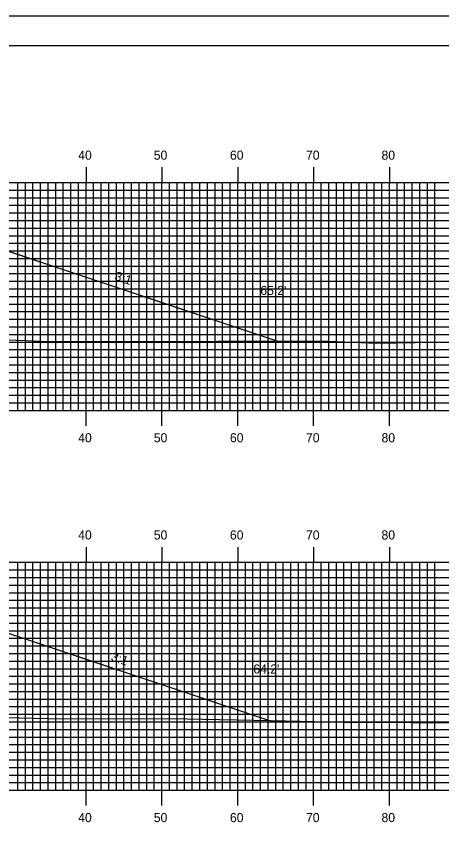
# Model space of a CAD drawing. Extents: x 1808226 to 1808569, y 442591 to 442811.
# Drawn here: x 1808422.1 to 1808478.2, y 442703.1 to 442810.5 of the extents above; entities that cross this region are included whole.
import ezdxf

# ---------------------------------------------------------------- set-up
doc = ezdxf.new("R2010")
doc.units = 0
for name, color, linetype in [('ANNOTATION', 7, 'Continuous'), ('BORDER', 7, 'Continuous'), ('D_Roadway_Centerline', 7, 'Continuous'), ('D_Roadway_SlopeLines', 7, 'Continuous'), ('D_Text_Standard', 7, 'Continuous'), ('H_V ANNOTATION', 7, 'Continuous'), ('MAJOR', 7, 'Continuous'), ('MINOR', 7, 'Continuous'), ('PLOT BOUNDARY', 7, 'Continuous'), ('S_Roadway_Centerline', 7, 'Continuous')]:
    doc.layers.add(name, color=color, linetype=linetype)

msp = doc.modelspace()

# ---------------------------------------------------------------- linework, layer by layer
at = {"layer": 'BORDER'}
msp.add_lwpolyline([(1808241.7, 442596.67), (1808561.7, 442596.67), (1808561.7, 442806.67), (1808241.7, 442806.67)], close=True, dxfattribs=at)
at = {"layer": 'D_Roadway_Centerline'}
for points in [[(1808328.57, 442769.16), (1808357.86, 442778.92), (1808359.81, 442779.41), (1808369.86, 442781.92), (1808379.3, 442782.3), (1808391.3, 442782.54), (1808403.3, 442782.3), (1808411.3, 442781.98), (1808414.3, 442781.86), (1808421.57, 442779.44), (1808456.46, 442767.81)], [(1808333.28, 442720.03), (1808359.3, 442728.7), (1808361.12, 442729.16), (1808371.3, 442731.7), (1808379.3, 442732.02), (1808391.3, 442732.26), (1808403.3, 442732.02), (1808411.3, 442731.7), (1808414.3, 442731.58), (1808421.57, 442729.16), (1808455.49, 442717.85)]]:
    msp.add_lwpolyline(points, dxfattribs=at)
at = {"layer": 'D_Roadway_SlopeLines'}
for points in [[(1808414.3, 442781.86), (1808456.46, 442767.81)], [(1808414.3, 442731.58), (1808455.49, 442717.85)]]:
    msp.add_lwpolyline(points, dxfattribs=at)
at = {"layer": 'MAJOR'}
for p, q in [((1808431.3, 442790.67), (1808431.3, 442788.67)), ((1808441.3, 442790.67), (1808441.3, 442788.67)), ((1808451.3, 442790.67), (1808451.3, 442788.67)), ((1808461.3, 442790.67), (1808461.3, 442788.67)), ((1808471.3, 442790.67), (1808471.3, 442788.67)), ((1808251.3, 442788.67), (1808531.3, 442788.67)), ((1808251.3, 442788.67), (1808531.3, 442788.67)), ((1808431.3, 442758.67), (1808431.3, 442788.67)), ((1808441.3, 442758.67), (1808441.3, 442788.67)), ((1808451.3, 442758.67), (1808451.3, 442788.67)), ((1808461.3, 442758.67), (1808461.3, 442788.67)), ((1808471.3, 442758.67), (1808471.3, 442788.67)), ((1808251.3, 442783.67), (1808531.3, 442783.67)), ((1808251.3, 442778.67), (1808531.3, 442778.67)), ((1808251.3, 442773.67), (1808531.3, 442773.67)), ((1808251.3, 442768.67), (1808531.3, 442768.67)), ((1808251.3, 442763.67), (1808531.3, 442763.67)), ((1808251.3, 442758.67), (1808531.3, 442758.67)), ((1808251.3, 442758.67), (1808531.3, 442758.67)), ((1808431.3, 442756.66), (1808431.3, 442758.67)), ((1808441.3, 442756.66), (1808441.3, 442758.67)), ((1808451.3, 442756.66), (1808451.3, 442758.67)), ((1808461.3, 442756.66), (1808461.3, 442758.67)), ((1808471.3, 442756.66), (1808471.3, 442758.67)), ((1808431.3, 442740.67), (1808431.3, 442738.67)), ((1808441.3, 442740.67), (1808441.3, 442738.67)), ((1808451.3, 442740.67), (1808451.3, 442738.67)), ((1808461.3, 442740.67), (1808461.3, 442738.67)), ((1808471.3, 442740.67), (1808471.3, 442738.67)), ((1808251.3, 442738.67), (1808531.3, 442738.67)), ((1808251.3, 442738.67), (1808531.3, 442738.67)), ((1808431.3, 442708.67), (1808431.3, 442738.67)), ((1808441.3, 442708.67), (1808441.3, 442738.67)), ((1808451.3, 442708.67), (1808451.3, 442738.67)), ((1808461.3, 442708.67), (1808461.3, 442738.67)), ((1808471.3, 442708.67), (1808471.3, 442738.67)), ((1808251.3, 442733.67), (1808531.3, 442733.67)), ((1808251.3, 442728.67), (1808531.3, 442728.67)), ((1808251.3, 442723.67), (1808531.3, 442723.67)), ((1808251.3, 442718.67), (1808531.3, 442718.67)), ((1808251.3, 442713.67), (1808531.3, 442713.67)), ((1808251.3, 442708.67), (1808531.3, 442708.67)), ((1808251.3, 442708.67), (1808531.3, 442708.67)), ((1808431.3, 442706.66), (1808431.3, 442708.67)), ((1808441.3, 442706.66), (1808441.3, 442708.67)), ((1808451.3, 442706.66), (1808451.3, 442708.67)), ((1808461.3, 442706.66), (1808461.3, 442708.67)), ((1808471.3, 442706.66), (1808471.3, 442708.67))]:
    msp.add_line(p, q, dxfattribs=at)
at = {"layer": 'MINOR'}
for p, q in [((1808422.3, 442758.67), (1808422.3, 442788.67)), ((1808423.3, 442758.67), (1808423.3, 442788.67)), ((1808424.3, 442758.67), (1808424.3, 442788.67)), ((1808425.3, 442758.67), (1808425.3, 442788.67)), ((1808426.3, 442758.67), (1808426.3, 442788.67)), ((1808427.3, 442758.67), (1808427.3, 442788.67)), ((1808428.3, 442758.67), (1808428.3, 442788.67)), ((1808429.3, 442758.67), (1808429.3, 442788.67)), ((1808430.3, 442758.67), (1808430.3, 442788.67)), ((1808432.3, 442758.67), (1808432.3, 442788.67)), ((1808433.3, 442758.67), (1808433.3, 442788.67)), ((1808434.3, 442758.67), (1808434.3, 442788.67)), ((1808435.3, 442758.67), (1808435.3, 442788.67)), ((1808436.3, 442758.67), (1808436.3, 442788.67)), ((1808437.3, 442758.67), (1808437.3, 442788.67)), ((1808438.3, 442758.67), (1808438.3, 442788.67)), ((1808439.3, 442758.67), (1808439.3, 442788.67)), ((1808440.3, 442758.67), (1808440.3, 442788.67)), ((1808442.3, 442758.67), (1808442.3, 442788.67)), ((1808443.3, 442758.67), (1808443.3, 442788.67)), ((1808444.3, 442758.67), (1808444.3, 442788.67)), ((1808445.3, 442758.67), (1808445.3, 442788.67)), ((1808446.3, 442758.67), (1808446.3, 442788.67)), ((1808447.3, 442758.67), (1808447.3, 442788.67)), ((1808448.3, 442758.67), (1808448.3, 442788.67)), ((1808449.3, 442758.67), (1808449.3, 442788.67)), ((1808450.3, 442758.67), (1808450.3, 442788.67)), ((1808452.3, 442758.67), (1808452.3, 442788.67)), ((1808453.3, 442758.67), (1808453.3, 442788.67)), ((1808454.3, 442758.67), (1808454.3, 442788.67)), ((1808455.3, 442758.67), (1808455.3, 442788.67)), ((1808456.3, 442758.67), (1808456.3, 442788.67)), ((1808457.3, 442758.67), (1808457.3, 442788.67)), ((1808458.3, 442758.67), (1808458.3, 442788.67)), ((1808459.3, 442758.67), (1808459.3, 442788.67)), ((1808460.3, 442758.67), (1808460.3, 442788.67)), ((1808462.3, 442758.67), (1808462.3, 442788.67)), ((1808463.3, 442758.67), (1808463.3, 442788.67)), ((1808464.3, 442758.67), (1808464.3, 442788.67)), ((1808465.3, 442758.67), (1808465.3, 442788.67)), ((1808466.3, 442758.67), (1808466.3, 442788.67)), ((1808467.3, 442758.67), (1808467.3, 442788.67)), ((1808468.3, 442758.67), (1808468.3, 442788.67)), ((1808469.3, 442758.67), (1808469.3, 442788.67)), ((1808470.3, 442758.67), (1808470.3, 442788.67)), ((1808472.3, 442758.67), (1808472.3, 442788.67)), ((1808473.3, 442758.67), (1808473.3, 442788.67)), ((1808474.3, 442758.67), (1808474.3, 442788.67)), ((1808475.3, 442758.67), (1808475.3, 442788.67)), ((1808476.3, 442758.67), (1808476.3, 442788.67)), ((1808477.3, 442758.67), (1808477.3, 442788.67)), ((1808251.3, 442787.67), (1808531.3, 442787.67)), ((1808251.3, 442786.67), (1808531.3, 442786.67)), ((1808251.3, 442785.67), (1808531.3, 442785.67)), ((1808251.3, 442784.67), (1808531.3, 442784.67)), ((1808251.3, 442782.67), (1808531.3, 442782.67)), ((1808251.3, 442781.67), (1808531.3, 442781.67)), ((1808251.3, 442780.67), (1808531.3, 442780.67)), ((1808251.3, 442779.67), (1808531.3, 442779.67)), ((1808251.3, 442777.67), (1808531.3, 442777.67)), ((1808251.3, 442776.67), (1808531.3, 442776.67)), ((1808251.3, 442775.67), (1808531.3, 442775.67)), ((1808251.3, 442774.67), (1808531.3, 442774.67)), ((1808251.3, 442772.67), (1808531.3, 442772.67)), ((1808251.3, 442771.67), (1808531.3, 442771.67)), ((1808251.3, 442770.67), (1808531.3, 442770.67)), ((1808251.3, 442769.67), (1808531.3, 442769.67)), ((1808251.3, 442767.67), (1808531.3, 442767.67)), ((1808251.3, 442766.67), (1808531.3, 442766.67)), ((1808251.3, 442765.67), (1808531.3, 442765.67)), ((1808251.3, 442764.67), (1808531.3, 442764.67)), ((1808251.3, 442762.67), (1808531.3, 442762.67)), ((1808251.3, 442761.67), (1808531.3, 442761.67)), ((1808251.3, 442760.67), (1808531.3, 442760.67)), ((1808251.3, 442759.67), (1808531.3, 442759.67)), ((1808422.3, 442708.67), (1808422.3, 442738.67)), ((1808423.3, 442708.67), (1808423.3, 442738.67)), ((1808424.3, 442708.67), (1808424.3, 442738.67)), ((1808425.3, 442708.67), (1808425.3, 442738.67)), ((1808426.3, 442708.67), (1808426.3, 442738.67)), ((1808427.3, 442708.67), (1808427.3, 442738.67)), ((1808428.3, 442708.67), (1808428.3, 442738.67)), ((1808429.3, 442708.67), (1808429.3, 442738.67)), ((1808430.3, 442708.67), (1808430.3, 442738.67)), ((1808432.3, 442708.67), (1808432.3, 442738.67)), ((1808433.3, 442708.67), (1808433.3, 442738.67)), ((1808434.3, 442708.67), (1808434.3, 442738.67)), ((1808435.3, 442708.67), (1808435.3, 442738.67)), ((1808436.3, 442708.67), (1808436.3, 442738.67)), ((1808437.3, 442708.67), (1808437.3, 442738.67)), ((1808438.3, 442708.67), (1808438.3, 442738.67)), ((1808439.3, 442708.67), (1808439.3, 442738.67)), ((1808440.3, 442708.67), (1808440.3, 442738.67)), ((1808442.3, 442708.67), (1808442.3, 442738.67)), ((1808443.3, 442708.67), (1808443.3, 442738.67)), ((1808444.3, 442708.67), (1808444.3, 442738.67)), ((1808445.3, 442708.67), (1808445.3, 442738.67)), ((1808446.3, 442708.67), (1808446.3, 442738.67)), ((1808447.3, 442708.67), (1808447.3, 442738.67)), ((1808448.3, 442708.67), (1808448.3, 442738.67)), ((1808449.3, 442708.67), (1808449.3, 442738.67)), ((1808450.3, 442708.67), (1808450.3, 442738.67)), ((1808452.3, 442708.67), (1808452.3, 442738.67)), ((1808453.3, 442708.67), (1808453.3, 442738.67)), ((1808454.3, 442708.67), (1808454.3, 442738.67)), ((1808455.3, 442708.67), (1808455.3, 442738.67)), ((1808456.3, 442708.67), (1808456.3, 442738.67)), ((1808457.3, 442708.67), (1808457.3, 442738.67)), ((1808458.3, 442708.67), (1808458.3, 442738.67)), ((1808459.3, 442708.67), (1808459.3, 442738.67)), ((1808460.3, 442708.67), (1808460.3, 442738.67)), ((1808462.3, 442708.67), (1808462.3, 442738.67)), ((1808463.3, 442708.67), (1808463.3, 442738.67)), ((1808464.3, 442708.67), (1808464.3, 442738.67)), ((1808465.3, 442708.67), (1808465.3, 442738.67)), ((1808466.3, 442708.67), (1808466.3, 442738.67)), ((1808467.3, 442708.67), (1808467.3, 442738.67)), ((1808468.3, 442708.67), (1808468.3, 442738.67)), ((1808469.3, 442708.67), (1808469.3, 442738.67)), ((1808470.3, 442708.67), (1808470.3, 442738.67)), ((1808472.3, 442708.67), (1808472.3, 442738.67)), ((1808473.3, 442708.67), (1808473.3, 442738.67)), ((1808474.3, 442708.67), (1808474.3, 442738.67)), ((1808475.3, 442708.67), (1808475.3, 442738.67)), ((1808476.3, 442708.67), (1808476.3, 442738.67)), ((1808477.3, 442708.67), (1808477.3, 442738.67)), ((1808251.3, 442737.67), (1808531.3, 442737.67)), ((1808251.3, 442736.67), (1808531.3, 442736.67)), ((1808251.3, 442735.67), (1808531.3, 442735.67)), ((1808251.3, 442734.67), (1808531.3, 442734.67)), ((1808251.3, 442732.67), (1808531.3, 442732.67)), ((1808251.3, 442731.67), (1808531.3, 442731.67)), ((1808251.3, 442730.67), (1808531.3, 442730.67)), ((1808251.3, 442729.67), (1808531.3, 442729.67)), ((1808251.3, 442727.67), (1808531.3, 442727.67)), ((1808251.3, 442726.67), (1808531.3, 442726.67)), ((1808251.3, 442725.67), (1808531.3, 442725.67)), ((1808251.3, 442724.67), (1808531.3, 442724.67)), ((1808251.3, 442722.67), (1808531.3, 442722.67)), ((1808251.3, 442721.67), (1808531.3, 442721.67)), ((1808251.3, 442720.67), (1808531.3, 442720.67)), ((1808251.3, 442719.67), (1808531.3, 442719.67)), ((1808251.3, 442717.67), (1808531.3, 442717.67)), ((1808251.3, 442716.67), (1808531.3, 442716.67)), ((1808251.3, 442715.67), (1808531.3, 442715.67)), ((1808251.3, 442714.67), (1808531.3, 442714.67)), ((1808251.3, 442712.67), (1808531.3, 442712.67)), ((1808251.3, 442711.67), (1808531.3, 442711.67)), ((1808251.3, 442710.67), (1808531.3, 442710.67)), ((1808251.3, 442709.67), (1808531.3, 442709.67))]:
    msp.add_line(p, q, dxfattribs=at)
at = {"layer": 'PLOT BOUNDARY'}
msp.add_lwpolyline([(1808225.51, 442590.55), (1808565.51, 442590.55), (1808565.51, 442810.55), (1808225.51, 442810.55)], close=True, dxfattribs=at)
at = {"layer": 'S_Roadway_Centerline'}
for points in [[(1808324.68, 442769.2), (1808341.69, 442769.04), (1808350.51, 442768.98), (1808362.69, 442768.77), (1808375.74, 442768.72), (1808380.4, 442768.65), (1808384.37, 442768.55), (1808392.46, 442768.41), (1808401.68, 442768.65), (1808403.84, 442768.71), (1808405.46, 442768.59), (1808426.54, 442767.72), (1808428.01, 442767.72), (1808438.5, 442767.73), (1808448.66, 442767.8), (1808453.86, 442767.8), (1808462.2, 442767.83), (1808469.65, 442767.52), (1808484.82, 442767.78), (1808489.8, 442767.63), (1808504.34, 442767.39), (1808512.6, 442767.29), (1808530.86, 442766.49), (1808531.3, 442766.48)], [(1808339.72, 442720), (1808340.32, 442720), (1808341.08, 442719.99), (1808360.9, 442719.6), (1808366.58, 442719.51), (1808382.67, 442719.22), (1808392.95, 442718.87), (1808399.05, 442718.65), (1808404.19, 442718.59), (1808418.28, 442718.29), (1808422.5, 442718.19), (1808426.22, 442718.09), (1808444.65, 442718.06), (1808446.64, 442718.04), (1808455.66, 442717.85), (1808467.21, 442717.6), (1808469.52, 442717.62), (1808489.02, 442717.46), (1808492.33, 442717.3), (1808495.71, 442717.45), (1808509.49, 442717.54), (1808521.65, 442717.28), (1808527.34, 442717.15), (1808531.3, 442717.12)]]:
    msp.add_lwpolyline(points, dxfattribs=at)

# ---------------------------------------------------------------- texts
at = {"layer": 'ANNOTATION'}
for p in [(1808434.98, 442775.87), (1808434.5, 442725.76)]:
    msp.add_text('3:1', height=1.2, rotation=341.5651, dxfattribs=at).set_placement(p)
at = {"layer": 'D_Text_Standard'}
for s, p in [("65.2'", (1808454.28, 442773.86)), ("64.2'", (1808453.36, 442724.03))]:
    msp.add_text(s, height=1.2, dxfattribs=at).set_placement(p)
at = {"layer": 'H_V ANNOTATION'}
for s, p in [('40', (1808430.27, 442791.67)), ('50', (1808440.23, 442791.67)), ('60', (1808450.27, 442791.67)), ('70', (1808460.3, 442791.67)), ('80', (1808470.25, 442791.67)), ('40', (1808430.27, 442754.47)), ('50', (1808440.23, 442754.47)), ('60', (1808450.27, 442754.47)), ('70', (1808460.3, 442754.47)), ('80', (1808470.25, 442754.47)), ('40', (1808430.27, 442741.67)), ('50', (1808440.23, 442741.67)), ('60', (1808450.27, 442741.67)), ('70', (1808460.3, 442741.67)), ('80', (1808470.25, 442741.67)), ('40', (1808430.27, 442704.47)), ('50', (1808440.23, 442704.47)), ('60', (1808450.27, 442704.47)), ('70', (1808460.3, 442704.47)), ('80', (1808470.25, 442704.47))]:
    msp.add_text(s, height=1.2, dxfattribs=at).set_placement(p)

doc.saveas('drawing.dxf')
